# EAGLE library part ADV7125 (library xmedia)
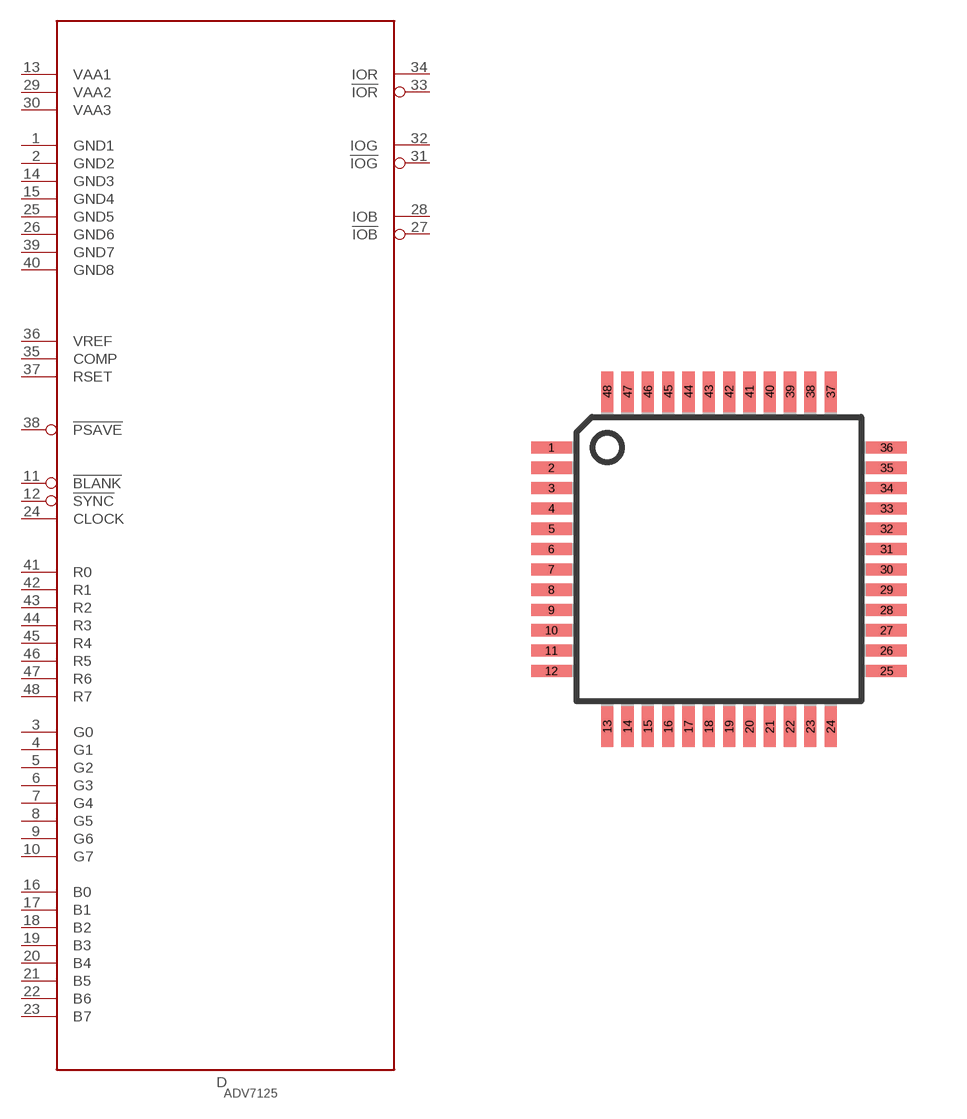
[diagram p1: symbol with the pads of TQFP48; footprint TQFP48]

Designator prefix D

## ADV7125  [TQFP48]
1  GND1  sup
2  GND2  sup
3  G0  in
4  G1  in
5  G2  in
6  G3  in
7  G4  in
8  G5  in
9  G6  in
10  G7  in
11  !BLANK  in
12  !SYNC  in
13  VAA1  sup
14  GND3  sup
15  GND4  sup
16  B0  in
17  B1  in
18  B2  in
19  B3  in
20  B4  in
21  B5  in
22  B6  in
23  B7  in
24  CLOCK  in
25  GND5  sup
26  GND6  sup
27  !IOB
28  IOB  out
29  VAA2  sup
30  VAA3  sup
31  !IOG
32  IOG  out
33  !IOR
34  IOR  out
35  COMP
36  VREF
37  RSET
38  !PSAVE  in
39  GND7  sup
40  GND8  sup
41  R0  in
42  R1  in
43  R2  in
44  R3  in
45  R4  in
46  R5  in
47  R6  in
48  R7  in

## Footprint TQFP48 (pad centres in mm)
Thin Plasic Quad Flat Package
smd 1.016 x 0.305: 1 -4.191,2.794; 2 -4.191,2.286; 3 -4.191,1.778; 4 -4.191,1.27; 5 -4.191,0.762; 6 -4.191,0.254; 7 -4.191,-0.254; 8 -4.191,-0.762; 9 -4.191,-1.27; 10 -4.191,-1.778; 11 -4.191,-2.286; 12 -4.191,-2.794; 25 4.191,-2.794; 26 4.191,-2.286; 27 4.191,-1.778; 28 4.191,-1.27; 29 4.191,-0.762; 30 4.191,-0.254; 31 4.191,0.254; 32 4.191,0.762; 33 4.191,1.27; 34 4.191,1.778; 35 4.191,2.286; 36 4.191,2.794
smd 0.305 x 1.016: 13 -2.794,-4.191; 14 -2.286,-4.191; 15 -1.778,-4.191; 16 -1.27,-4.191; 17 -0.762,-4.191; 18 -0.254,-4.191; 19 0.254,-4.191; 20 0.762,-4.191; 21 1.27,-4.191; 22 1.778,-4.191; 23 2.286,-4.191; 24 2.794,-4.191; 37 2.794,4.191; 38 2.286,4.191; 39 1.778,4.191; 40 1.27,4.191; 41 0.762,4.191; 42 0.254,4.191; 43 -0.254,4.191; 44 -0.762,4.191; 45 -1.27,4.191; 46 -1.778,4.191; 47 -2.286,4.191; 48 -2.794,4.191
